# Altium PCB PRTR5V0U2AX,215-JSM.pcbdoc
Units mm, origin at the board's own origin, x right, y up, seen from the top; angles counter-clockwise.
Board outline 16.24 x 16.21 mm, 2 copper layers (Top Layer, Bottom Layer), stack 0 mm thick; 1 components, 0 nets, 4 pads, 0 vias.
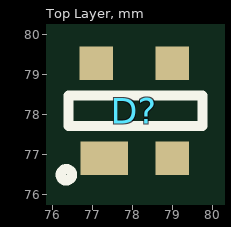
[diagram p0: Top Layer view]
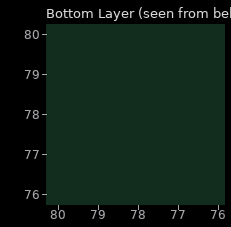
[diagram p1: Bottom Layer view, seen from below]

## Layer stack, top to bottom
Top Layer: signal copper (thickness not stored)
Bottom Layer: signal copper (thickness not stored)

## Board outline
86.091,69.85 69.85,69.85 69.85,86.061 86.091,86.061

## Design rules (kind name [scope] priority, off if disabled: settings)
PasteMaskExpansion "Paste Mask Expansion" [All] p1: expansion=0
SolderMaskExpansion "Solder Mask Expansion" [IsVia] p1: expansion=-25.4 istentingtop=TRUE
SolderMaskExpansion "Solder Mask Expansion" [All] p2: expansion=0.051 istentingtop=FALSE

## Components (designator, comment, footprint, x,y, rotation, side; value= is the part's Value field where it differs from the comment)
D? "PRTR5V0U2AX,215-JSM" SOT-143-4_L2.9-W1.3-P1.92-LS2.3-BL 78.041,78.1 r0 top

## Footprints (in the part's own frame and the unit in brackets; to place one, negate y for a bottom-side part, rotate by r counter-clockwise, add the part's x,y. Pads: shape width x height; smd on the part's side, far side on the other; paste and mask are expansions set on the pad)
SOT-143-4_L2.9-W1.3-P1.92-LS2.3-BL [mil]
  rect 47x33 smd: 1(-29.53,-46.91)
  rect 33x33 smd: 2(37.4,-46.91) 3(37.4,46.9) 4(-37.4,46.9)
  silkscreen extent -72,-69 67,15

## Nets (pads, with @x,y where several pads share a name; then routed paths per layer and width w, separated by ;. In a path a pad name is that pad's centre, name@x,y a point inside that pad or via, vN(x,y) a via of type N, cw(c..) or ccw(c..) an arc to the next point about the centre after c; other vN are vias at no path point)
pads on no net: D?.1 D?.2 D?.3 D?.4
